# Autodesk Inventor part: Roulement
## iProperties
Shininess: 64.0
Length Units: 11269
Angle Units: 11279
Time Units: 11290
Mass Units: 11283
Length Display Precision: 3
Angle Display Precision: 2
Compacted: True
Part Number: Roulement
Document SubType Name: Modeling
Created: 2005-01
Material: Par défaut
Designer: lolo (Laurent Moretti)
Density: 0.0
Volumn: 0.0
Area: 0.0
PropertySet Name: Model Information
Control State: 0
Master: False
Checked Out: False
Author: lolo (Laurent Moretti)
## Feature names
1. Base1
